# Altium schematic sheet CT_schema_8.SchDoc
size 254 x 194 mm
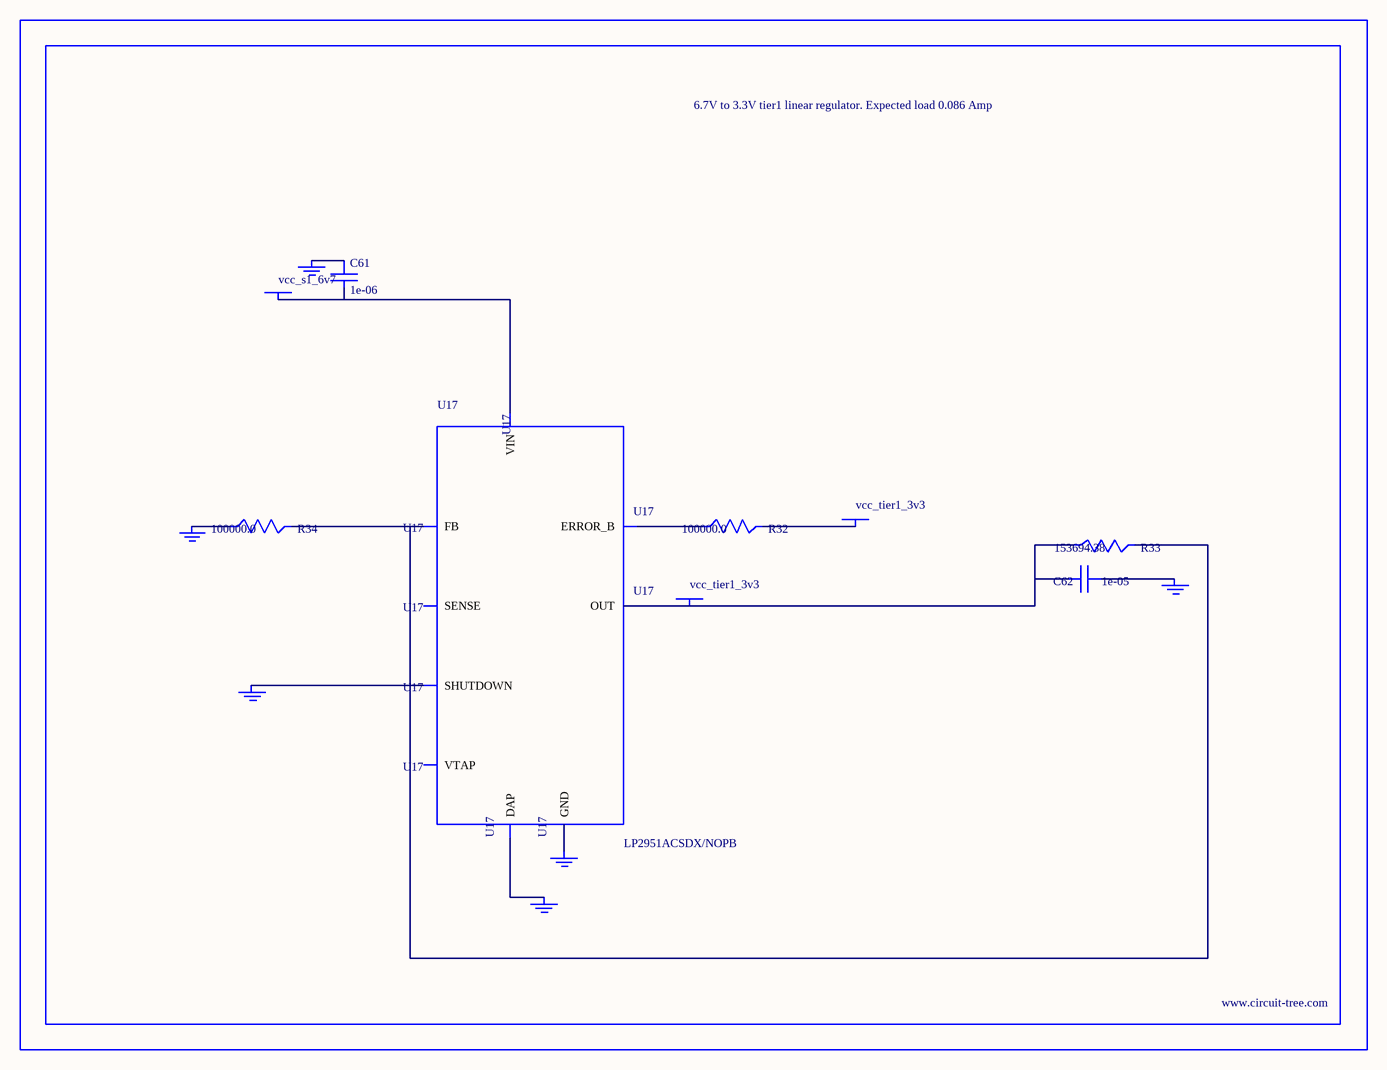
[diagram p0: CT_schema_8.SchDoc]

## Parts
BORDER7  (no value)
C61  1e-06  [C0603]
C62  1e-05  [C1210]
GND_INSTANCE_7_0  (no value)
GND_INSTANCE_7_1  (no value)
GND_INSTANCE_7_2  (no value)
GND_INSTANCE_7_3  (no value)
GND_INSTANCE_7_4  (no value)
GND_INSTANCE_7_5  (no value)
POWER_INSTANCE_7_0  vcc_tier1_3v3
POWER_INSTANCE_7_1  vcc_s1_6v7
POWER_INSTANCE_7_2  vcc_tier1_3v3
R32  100000.0  [R0603]
R33  153694.38  [R0603]
R34  100000.0  [R0603]
U17  LP2951ACSDX/NOPB  [WSON-8]

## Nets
NetC61_1: C61.1 GND_INSTANCE_7_3.0(GND)
NetC61_2: C61.2 POWER_INSTANCE_7_1.0(PWR) U17.8(VIN)
NetC62_1: C62.1 GND_INSTANCE_7_0.0(GND)
NetC62_2: C62.2 POWER_INSTANCE_7_2.0(PWR) R33.1 U17.1(OUT)
NetGND_INSTANCE_7_1_0: GND_INSTANCE_7_1.0(GND) U17.3(SHUTDOWN)
NetGND_INSTANCE_7_2_0: GND_INSTANCE_7_2.0(GND) R34.1
NetGND_INSTANCE_7_4_0: GND_INSTANCE_7_4.0(GND) U17.PAD(DAP)
NetGND_INSTANCE_7_5_0: GND_INSTANCE_7_5.0(GND) U17.4(GND)
NetPOWER_INSTANCE_7_0_0: POWER_INSTANCE_7_0.0(PWR) R32.2
NetR32_1: R32.1 U17.5(ERROR_B)
NetR33_2: R33.2 R34.2 U17.7(FB)

Not connected (* = marked no-connect by the designer): U17 2(SENSE) 6(VTAP)

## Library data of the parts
BORDER7 = BORDER_PAGE7
C61 = C0603C105K3RACTU
C62 = GRM32DR61E106MA12L
GND_INSTANCE_7_0-GND_INSTANCE_7_5 = GND
POWER_INSTANCE_7_0-POWER_INSTANCE_7_2 = PWR
R32 R34 = RC0603JR-07100KL
R33 = R33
